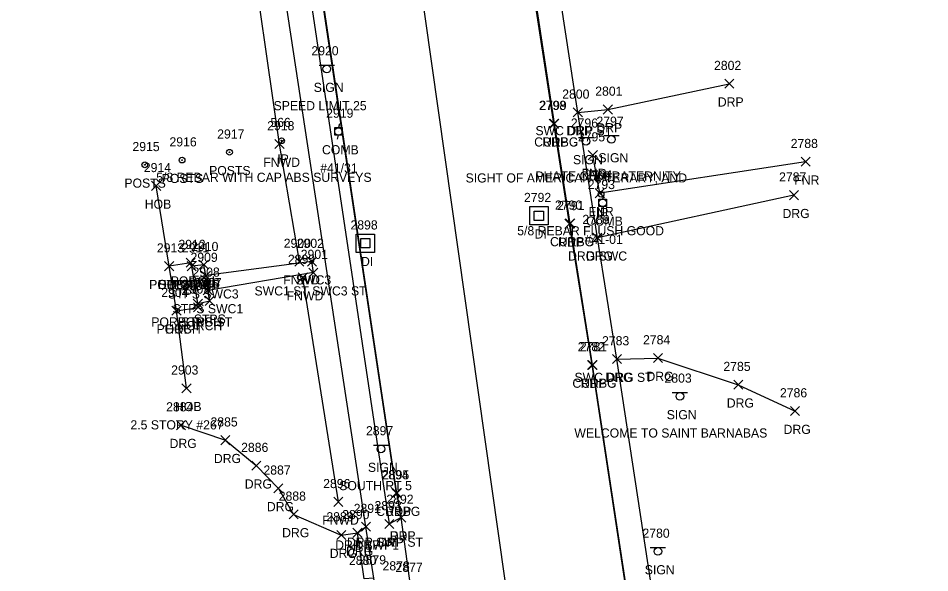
# Model space of a CAD drawing. Extents: x 1690689 to 1696275, y 438760 to 444007.
# Drawn here: x 1691078.4 to 1691277.8, y 441895.7 to 442017 of the extents above; entities that cross this region are included whole.
import ezdxf

# ---------------------------------------------------------------- set-up
doc = ezdxf.new("R2010")
doc.units = 0
for name, color, linetype in [('D_A', 7, 'Continuous'), ('D_I', 7, 'Continuous'), ('DS', 7, 'Continuous'), ('L_A', 7, 'Continuous'), ('L_C', 7, 'Continuous'), ('L_I', 7, 'Continuous'), ('L_TIC', 7, 'Continuous'), ('LBC', 7, 'Continuous'), ('LBF', 7, 'Continuous'), ('LFNC', 7, 'Continuous'), ('LPST', 7, 'Continuous'), ('M_A', 7, 'Continuous'), ('M_C', 7, 'Continuous'), ('M_I', 7, 'Continuous'), ('MPIR', 7, 'Continuous'), ('P_A', 7, 'Continuous'), ('P_I', 7, 'Continuous'), ('P_TIC', 7, 'Continuous'), ('PET', 7, 'Continuous'), ('PRC', 7, 'Continuous'), ('R_A', 7, 'Continuous'), ('R_I', 7, 'Continuous'), ('R_TIC', 7, 'Continuous'), ('RC', 7, 'Continuous'), ('RDG', 7, 'Continuous'), ('RDP', 7, 'Continuous'), ('RSW', 7, 'Continuous'), ('S_A', 7, 'Continuous'), ('S_C', 7, 'Continuous'), ('S_I', 7, 'Continuous'), ('SSGN', 7, 'Continuous'), ('U_A', 7, 'Continuous'), ('U_C', 7, 'Continuous'), ('U_I', 7, 'Continuous'), ('UP', 7, 'Continuous')]:
    doc.layers.add(name, color=color, linetype=linetype)

msp = doc.modelspace()

# ---------------------------------------------------------------- linework, layer by layer
at = {"layer": 'DS'}
for p, q in [((1691190.31, 441975.75), (1691194.31, 441975.75)), ((1691190.31, 441971.75), (1691190.31, 441975.75)), ((1691191.31, 441972.75), (1691191.31, 441974.75)), ((1691191.31, 441974.75), (1691193.31, 441974.75)), ((1691193.31, 441974.75), (1691193.31, 441972.75)), ((1691194.31, 441975.75), (1691194.31, 441971.75)), ((1691193.31, 441972.75), (1691191.31, 441972.75)), ((1691192.31, 441973.76), (1691192.31, 441973.76)), ((1691192.31, 441973.76), (1691192.31, 441973.76)), ((1691194.31, 441971.75), (1691190.31, 441971.75)), ((1691152.36, 441969.75), (1691156.36, 441969.75)), ((1691152.36, 441965.75), (1691152.36, 441969.75)), ((1691153.36, 441966.75), (1691153.36, 441968.75)), ((1691153.36, 441968.75), (1691155.36, 441968.75)), ((1691155.36, 441968.75), (1691155.36, 441966.75)), ((1691156.36, 441969.75), (1691156.36, 441965.75)), ((1691155.36, 441966.75), (1691153.36, 441966.75)), ((1691154.37, 441967.75), (1691154.37, 441967.75)), ((1691154.37, 441967.75), (1691154.37, 441967.75)), ((1691156.36, 441965.75), (1691152.36, 441965.75))]:
    msp.add_line(p, q, dxfattribs=at)
at = {"layer": 'L_TIC'}
for points in [[(1691134.58, 441988.45), (1691136.58, 441990.45)], [(1691136.58, 441988.45), (1691134.58, 441990.45)], [(1691203.11, 441986.02), (1691205.11, 441988.02)], [(1691205.11, 441986.02), (1691203.11, 441988.02)], [(1691249.65, 441984.57), (1691251.65, 441986.57)], [(1691251.65, 441984.57), (1691249.65, 441986.57)], [(1691107.6, 441979.3), (1691109.6, 441981.3)], [(1691109.6, 441979.3), (1691107.6, 441981.3)], [(1691204.66, 441977.7), (1691206.66, 441979.7)], [(1691206.66, 441977.7), (1691204.66, 441979.7)], [(1691115.17, 441962.49), (1691117.17, 441964.49)], [(1691117.17, 441962.49), (1691115.17, 441964.49)], [(1691118.05, 441962.04), (1691120.05, 441964.04)], [(1691120.05, 441962.04), (1691118.05, 441964.04)], [(1691138.93, 441962.74), (1691140.93, 441964.74)], [(1691140.93, 441962.74), (1691138.93, 441964.74)], [(1691110.45, 441961.72), (1691112.45, 441963.72)], [(1691112.45, 441961.72), (1691110.45, 441963.72)], [(1691110.45, 441961.72), (1691112.45, 441963.72)], [(1691112.45, 441961.72), (1691110.45, 441963.72)], [(1691115.38, 441961.72), (1691117.38, 441963.72)], [(1691117.38, 441961.72), (1691115.38, 441963.72)], [(1691115.38, 441961.72), (1691117.38, 441963.72)], [(1691117.38, 441961.72), (1691115.38, 441963.72)], [(1691118.47, 441959.66), (1691120.47, 441961.66)], [(1691120.47, 441959.66), (1691118.47, 441961.66)], [(1691139.69, 441959.24), (1691141.69, 441961.24)], [(1691141.69, 441959.24), (1691139.69, 441961.24)], [(1691118.91, 441956.43), (1691120.91, 441958.43)], [(1691120.91, 441956.43), (1691118.91, 441958.43)], [(1691119.33, 441954.15), (1691121.33, 441956.15)], [(1691121.33, 441954.15), (1691119.33, 441956.15)], [(1691116.71, 441953.53), (1691118.71, 441955.53)], [(1691118.71, 441953.53), (1691116.71, 441955.53)], [(1691116.71, 441953.53), (1691118.71, 441955.53)], [(1691118.71, 441953.53), (1691116.71, 441955.53)], [(1691116.79, 441952.71), (1691118.79, 441954.71)], [(1691118.79, 441952.71), (1691116.79, 441954.71)], [(1691112.07, 441951.99), (1691114.07, 441953.99)], [(1691114.07, 441951.99), (1691112.07, 441953.99)], [(1691112.07, 441951.99), (1691114.07, 441953.99)], [(1691114.07, 441951.99), (1691112.07, 441953.99)], [(1691114.23, 441935.02), (1691116.23, 441937.02)], [(1691116.23, 441935.02), (1691114.23, 441937.02)], [(1691147.46, 441910.18), (1691149.46, 441912.18)], [(1691149.46, 441910.18), (1691147.46, 441912.18)]]:
    msp.add_lwpolyline(points, dxfattribs=at)
at = {"layer": 'LBC'}
msp.add_lwpolyline([(1691115.23, 441936.02), (1691113.07, 441952.99), (1691111.45, 441962.72), (1691108.6, 441980.3)], dxfattribs=at)
at = {"layer": 'LBF'}
for points in [[(1691113.07, 441952.99), (1691117.79, 441953.71), (1691117.71, 441954.53), (1691116.38, 441962.72), (1691116.17, 441963.49), (1691111.45, 441962.72)], [(1691117.71, 441954.53), (1691120.33, 441955.15), (1691119.91, 441957.43), (1691119.47, 441960.66), (1691119.05, 441963.04), (1691116.38, 441962.72)]]:
    msp.add_lwpolyline(points, dxfattribs=at)
at = {"layer": 'LFNC'}
for points in [[(1691139.93, 441963.74), (1691135.58, 441989.45), (1691128.48, 442038.64)], [(1691250.65, 441985.57), (1691205.66, 441978.7), (1691204.11, 441987.02)], [(1691148.46, 441911.18), (1691140.69, 441960.24)]]:
    msp.add_lwpolyline(points, dxfattribs=at)
at = {"layer": 'LPST'}
for centre, radius in [((1691124.65, 441987.64), 0.625), ((1691114.27, 441985.92), 0.625), ((1691114.27, 441985.92), 0.0833), ((1691124.65, 441987.64), 0.0833), ((1691106.12, 441984.89), 0.625), ((1691106.12, 441984.89), 0.0833)]:
    msp.add_circle(centre, radius, dxfattribs=at)
at = {"layer": 'MPIR'}
for centre, radius in [((1691136.04, 441990.17), 0.625), ((1691136.04, 441990.17), 0.0833), ((1691205.92, 441978.48), 0.625), ((1691205.92, 441978.48), 0.0833)]:
    msp.add_circle(centre, radius, dxfattribs=at)
at = {"layer": 'P_TIC'}
for points in [[(1691194.58, 441992.9), (1691196.58, 441994.9)], [(1691196.58, 441992.9), (1691194.58, 441994.9)], [(1691198.02, 441970.98), (1691200.02, 441972.98)], [(1691200.02, 441970.98), (1691198.02, 441972.98)], [(1691202.96, 441940.11), (1691204.96, 441942.11)], [(1691204.96, 441940.11), (1691202.96, 441942.11)], [(1691160.27, 441912.09), (1691162.27, 441914.09)], [(1691162.27, 441912.09), (1691160.27, 441914.09)], [(1691161.22, 441906.75), (1691163.22, 441908.75)], [(1691163.22, 441906.75), (1691161.22, 441908.75)]]:
    msp.add_lwpolyline(points, dxfattribs=at)
at = {"layer": 'PET'}
for points in [[(1691198.82, 441652.13), (1691193.05, 441693.14), (1691192.27, 441697.79), (1691180.43, 441782.55), (1691179.29, 441788.61), (1691177.08, 441805.24), (1691176.38, 441809.81), (1691165.21, 441886.02), (1691164.21, 441892.86), (1691162.22, 441907.75), (1691161.27, 441913.09), (1691143.08, 442034.41), (1691142.3, 442039.49), (1691139.9, 442054.44), (1691139.08, 442060.8), (1691125.85, 442150.15)], [(1691238.35, 441622.76), (1691233.07, 441677.78), (1691233.21, 441686.68), (1691232.89, 441704.26), (1691235.54, 441724.07), (1691224.38, 441802.5), (1691215.77, 441863.02), (1691203.96, 441941.11), (1691199.02, 441971.98), (1691195.58, 441993.9), (1691190.73, 442025.64), (1691172.95, 442147.3)]]:
    msp.add_lwpolyline(points, dxfattribs=at)
at = {"layer": 'PRC'}
msp.add_lwpolyline([(1691277.81, 441080.96), (1691253.5, 441214.94), (1691246.19, 441267.52), (1691239.79, 441327.83), (1691235.79, 441375.29), (1691233.27, 441422.2), (1691229.73, 441505.18), (1691226.6, 441557.92), (1691222.02, 441618.83), (1691218.57, 441657.04), (1691144.02, 442182.42), (1691112.43, 442376.83), (1691097.75, 442454.48), (1691089.73, 442499.13), (1691078.44, 442565.84)], dxfattribs=at)
at = {"layer": 'R_TIC'}
for points in [[(1691232.96, 442001.64), (1691234.96, 442003.64)], [(1691234.96, 442001.64), (1691232.96, 442003.64)], [(1691206.41, 441996.01), (1691208.41, 441998.01)], [(1691208.41, 441996.01), (1691206.41, 441998.01)], [(1691199.85, 441995.37), (1691201.85, 441997.37)], [(1691201.85, 441995.37), (1691199.85, 441997.37)], [(1691199.85, 441995.37), (1691201.85, 441997.37)], [(1691201.85, 441995.37), (1691199.85, 441997.37)], [(1691194.71, 441992.9), (1691196.71, 441994.9)], [(1691196.71, 441992.9), (1691194.71, 441994.9)], [(1691194.71, 441992.9), (1691196.71, 441994.9)], [(1691196.71, 441992.9), (1691194.71, 441994.9)], [(1691247.11, 441977.25), (1691249.11, 441979.25)], [(1691249.11, 441977.25), (1691247.11, 441979.25)], [(1691198.16, 441971.09), (1691200.16, 441973.09)], [(1691200.16, 441971.09), (1691198.16, 441973.09)], [(1691198.16, 441971.09), (1691200.16, 441973.09)], [(1691200.16, 441971.09), (1691198.16, 441973.09)], [(1691204.1, 441967.95), (1691206.1, 441969.95)], [(1691206.1, 441967.95), (1691204.1, 441969.95)], [(1691204.1, 441967.95), (1691206.1, 441969.95)], [(1691206.1, 441967.95), (1691204.1, 441969.95)], [(1691141.69, 441962.73), (1691143.69, 441964.73)], [(1691143.69, 441962.73), (1691141.69, 441964.73)], [(1691142, 441960.32), (1691144, 441962.32)], [(1691144, 441960.32), (1691142, 441962.32)], [(1691142, 441960.32), (1691144, 441962.32)], [(1691144, 441960.32), (1691142, 441962.32)], [(1691118.47, 441959.66), (1691120.47, 441961.66)], [(1691120.47, 441959.66), (1691118.47, 441961.66)], [(1691118.91, 441956.43), (1691120.91, 441958.43)], [(1691120.91, 441956.43), (1691118.91, 441958.43)], [(1691203.07, 441940.13), (1691205.07, 441942.13)], [(1691205.07, 441940.13), (1691203.07, 441942.13)], [(1691203.07, 441940.13), (1691205.07, 441942.13)], [(1691205.07, 441940.13), (1691203.07, 441942.13)], [(1691208.39, 441941.41), (1691210.39, 441943.41)], [(1691210.39, 441941.41), (1691208.39, 441943.41)], [(1691208.39, 441941.41), (1691210.39, 441943.41)], [(1691210.39, 441941.41), (1691208.39, 441943.41)], [(1691217.35, 441941.63), (1691219.35, 441943.63)], [(1691219.35, 441941.63), (1691217.35, 441943.63)], [(1691234.93, 441935.8), (1691236.93, 441937.8)], [(1691236.93, 441935.8), (1691234.93, 441937.8)], [(1691247.35, 441930.03), (1691249.35, 441932.03)], [(1691249.35, 441930.03), (1691247.35, 441932.03)], [(1691113.05, 441926.96), (1691115.05, 441928.96)], [(1691115.05, 441926.96), (1691113.05, 441928.96)], [(1691122.75, 441923.66), (1691124.75, 441925.66)], [(1691124.75, 441923.66), (1691122.75, 441925.66)], [(1691129.51, 441918.09), (1691131.51, 441920.09)], [(1691131.51, 441918.09), (1691129.51, 441920.09)], [(1691134.33, 441913.13), (1691136.33, 441915.13)], [(1691136.33, 441913.13), (1691134.33, 441915.13)], [(1691160.14, 441912.1), (1691162.14, 441914.1)], [(1691162.14, 441912.1), (1691160.14, 441914.1)], [(1691137.67, 441907.43), (1691139.67, 441909.43)], [(1691139.67, 441907.43), (1691137.67, 441909.43)], [(1691161.22, 441906.75), (1691163.22, 441908.75)], [(1691163.22, 441906.75), (1691161.22, 441908.75)], [(1691153.5, 441904.74), (1691155.5, 441906.74)], [(1691155.5, 441904.74), (1691153.5, 441906.74)], [(1691153.5, 441904.74), (1691155.5, 441906.74)], [(1691155.5, 441904.74), (1691153.5, 441906.74)], [(1691158.62, 441905.35), (1691160.62, 441907.35)], [(1691160.62, 441905.35), (1691158.62, 441907.35)], [(1691158.62, 441905.35), (1691160.62, 441907.35)], [(1691160.62, 441905.35), (1691158.62, 441907.35)], [(1691148.09, 441902.91), (1691150.09, 441904.91)], [(1691150.09, 441902.91), (1691148.09, 441904.91)], [(1691151.65, 441903.39), (1691153.65, 441905.39)], [(1691153.65, 441903.39), (1691151.65, 441905.39)], [(1691151.65, 441903.39), (1691153.65, 441905.39)], [(1691153.65, 441903.39), (1691151.65, 441905.39)]]:
    msp.add_lwpolyline(points, dxfattribs=at)
at = {"layer": 'RC'}
for points in [[(1691161.14, 441913.1), (1691142.92, 442034.4)], [(1691195.71, 441993.9), (1691190.89, 442025.7)], [(1691199.16, 441972.09), (1691195.71, 441993.9)], [(1691204.07, 441941.13), (1691199.16, 441972.09)], [(1691233.05, 441704.12), (1691235.66, 441723.91), (1691224.62, 441802.48), (1691215.9, 441863.01), (1691204.07, 441941.13)]]:
    msp.add_lwpolyline(points, dxfattribs=at)
at = {"layer": 'RDG'}
for points in [[(1691248.11, 441978.25), (1691205.1, 441968.95)], [(1691209.39, 441942.41), (1691218.35, 441942.63), (1691235.93, 441936.8), (1691248.35, 441931.03)], [(1691114.05, 441927.96), (1691123.75, 441924.66), (1691130.51, 441919.09), (1691135.33, 441914.13), (1691138.67, 441908.43), (1691149.09, 441903.91), (1691152.65, 441904.39)]]:
    msp.add_lwpolyline(points, dxfattribs=at)
at = {"layer": 'RDP'}
for points in [[(1691200.85, 441996.37), (1691207.41, 441997.01), (1691233.96, 442002.64)], [(1691162.22, 441907.75), (1691159.62, 441906.35)], [(1691156.2, 441894.49), (1691154.13, 441894.37), (1691152.65, 441904.39), (1691154.5, 441905.74)]]:
    msp.add_lwpolyline(points, dxfattribs=at)
at = {"layer": 'RSW'}
for points in [[(1691186.99, 441688.48), (1691175.94, 441757.23), (1691175.52, 441761.59), (1691171.12, 441789.95), (1691169.26, 441802.21), (1691162.18, 441853.19), (1691161.47, 441857.81), (1691156.2, 441894.49), (1691154.5, 441905.74), (1691133.83, 442041.33), (1691132.58, 442050.8), (1691127.44, 442084.38), (1691126.8, 442088.1), (1691113.62, 442174.46)], [(1691235.73, 441762.38), (1691230.02, 441803.11), (1691221.37, 441863.4), (1691209.39, 441942.41), (1691205.1, 441968.95), (1691200.85, 441996.37), (1691196.4, 442025.52), (1691180.16, 442136.25)], [(1691159.62, 441906.35), (1691139.69, 442039.88)], [(1691143, 441961.32), (1691142.69, 441963.73), (1691119.47, 441960.66)], [(1691143, 441961.32), (1691119.91, 441957.43)]]:
    msp.add_lwpolyline(points, dxfattribs=at)
at = {"layer": 'SSGN'}
for p, q in [((1691144.28, 442006.69), (1691147.61, 442006.69)), ((1691145.93, 442005.86), (1691145.93, 442005.86)), ((1691200.99, 441990.88), (1691204.32, 441990.88)), ((1691202.64, 441990.05), (1691202.64, 441990.05)), ((1691206.55, 441991.3), (1691209.88, 441991.3)), ((1691208.19, 441990.46), (1691208.19, 441990.46)), ((1691221.5, 441935.1), (1691224.83, 441935.1)), ((1691223.15, 441934.26), (1691223.15, 441934.26)), ((1691156.13, 441923.59), (1691159.46, 441923.59)), ((1691157.78, 441922.75), (1691157.78, 441922.75)), ((1691216.69, 441901.18), (1691220.02, 441901.18)), ((1691218.34, 441900.34), (1691218.34, 441900.34))]:
    msp.add_line(p, q, dxfattribs=at)
for centre in [(1691145.93, 442005.86), (1691202.64, 441990.05), (1691208.19, 441990.46), (1691223.15, 441934.26), (1691157.78, 441922.75), (1691218.34, 441900.34)]:
    msp.add_circle(centre, 0.833, dxfattribs=at)
at = {"layer": 'UP'}
for p, q in [((1691147.66, 441991.36), (1691147.66, 441993.03)), ((1691147.66, 441993.03), (1691149.32, 441993.03)), ((1691148.74, 441993.86), (1691148.49, 441993.03)), ((1691148.49, 441992.19), (1691148.49, 441992.19)), ((1691149.32, 441993.03), (1691149.32, 441991.36)), ((1691149.32, 441991.36), (1691147.66, 441991.36)), ((1691148.24, 441990.53), (1691148.49, 441991.36)), ((1691206.51, 441978.25), (1691206.26, 441977.42)), ((1691205.43, 441975.75), (1691205.43, 441977.42)), ((1691205.43, 441977.42), (1691207.09, 441977.42)), ((1691206.26, 441976.59), (1691206.26, 441976.59)), ((1691207.09, 441977.42), (1691207.09, 441975.75)), ((1691207.09, 441975.75), (1691205.43, 441975.75)), ((1691206.01, 441974.92), (1691206.26, 441975.75))]:
    msp.add_line(p, q, dxfattribs=at)
for centre in [(1691148.49, 441992.19), (1691206.26, 441976.59)]:
    msp.add_circle(centre, 0.833, dxfattribs=at)

# ---------------------------------------------------------------- texts
at = {"layer": 'D_A'}
for p in [(1691191.37, 441968.76), (1691153.42, 441962.75)]:
    msp.add_text('DI', height=2, dxfattribs=at).set_placement(p)
at = {"layer": 'D_I'}
for s, p in [('2792', (1691189.05, 441976.76)), ('2898', (1691151.11, 441970.75))]:
    msp.add_text(s, height=2, dxfattribs=at).set_placement(p)
at = {"layer": 'L_A'}
for s, p in [('FNWD', (1691132.05, 441984.45)), ('POSTS', (1691120.19, 441982.64)), ('FNR', (1691201.64, 441982.02)), ('POSTS', (1691101.66, 441979.89)), ('POSTS', (1691109.81, 441980.92)), ('FNR', (1691248.18, 441980.57)), ('HOB', (1691106.11, 441975.3)), ('FNR', (1691203.19, 441973.7)), ('PORCH', (1691111.79, 441958.49)), ('STPS', (1691115.57, 441958.04)), ('FNWD', (1691136.4, 441958.74)), ('PORCH', (1691107.07, 441957.72)), ('HOB', (1691108.95, 441957.72)), ('STPS POR', (1691109.08, 441957.72)), ('PORCH', (1691112, 441957.72)), ('STPS SWC3', (1691111.19, 441955.66)), ('FNWD', (1691137.15, 441955.24)), ('STPS SWC1', (1691112.19, 441952.43)), ('STPS', (1691116.85, 441950.15)), ('POR STPS ST', (1691107.54, 441949.53)), ('PORCH', (1691108.69, 441947.99)), ('HOB', (1691110.58, 441947.99)), ('PORCH', (1691113.33, 441949.53)), ('PORCH', (1691113.41, 441948.71)), ('HOB', (1691112.74, 441931.02)), ('FNWD', (1691144.92, 441906.18))]:
    msp.add_text(s, height=2, dxfattribs=at).set_placement(p)
at = {"layer": 'L_C'}
msp.add_text('2.5 STORY #267', height=2, dxfattribs=at).set_placement((1691102.98, 441927.02))
at = {"layer": 'L_I'}
for s, p in [('2918', (1691132.89, 441992.45)), ('2917', (1691121.96, 441990.64)), ('2795', (1691200.85, 441990.02)), ('2915', (1691103.42, 441987.89)), ('2916', (1691111.52, 441988.92)), ('2788', (1691247.39, 441988.57)), ('2914', (1691105.91, 441983.3)), ('2794', (1691202.4, 441981.7)), ('2912', (1691113.47, 441966.49)), ('2910', (1691116.27, 441966.04)), ('2900', (1691136.51, 441966.74)), ('2913', (1691108.76, 441965.72)), ('2913', (1691108.76, 441965.72)), ('2911', (1691114.25, 441965.72)), ('2911', (1691114.25, 441965.72)), ('2909', (1691116.12, 441963.66)), ('2899', (1691137.42, 441963.24)), ('2908', (1691116.57, 441960.43)), ('2907', (1691116.99, 441958.15)), ('2904', (1691109.73, 441955.99)), ('2904', (1691109.73, 441955.99)), ('2906', (1691114.31, 441957.53)), ('2906', (1691114.31, 441957.53)), ('2905', (1691114.45, 441956.71)), ('2903', (1691111.89, 441939.02)), ('2896', (1691145.14, 441914.18))]:
    msp.add_text(s, height=2, dxfattribs=at).set_placement(p)
at = {"layer": 'M_A'}
for p in [(1691135.09, 441985.17), (1691204.97, 441973.48)]:
    msp.add_text('IP', height=2, dxfattribs=at).set_placement(p)
at = {"layer": 'M_C'}
for s, p in [('5/8 REBAR WITH CAP ABS SURVEYS', (1691108.62, 441981.17)), ('5/8 REBAR FLUSH GOOD', (1691187.58, 441969.48))]:
    msp.add_text(s, height=2, dxfattribs=at).set_placement(p)
at = {"layer": 'M_I'}
for s, p in [('566', (1691133.58, 441993.17)), ('560', (1691203.43, 441981.48))]:
    msp.add_text(s, height=2, dxfattribs=at).set_placement(p)
at = {"layer": 'P_A'}
for p in [(1691193.06, 441988.9), (1691196.51, 441966.98), (1691201.45, 441936.11), (1691158.76, 441908.09), (1691159.7, 441902.75)]:
    msp.add_text('RDP', height=2, dxfattribs=at).set_placement(p)
at = {"layer": 'P_I'}
for s, p in [('2798', (1691192.32, 441996.9)), ('2791', (1691196.33, 441974.98)), ('2781', (1691201.27, 441944.11)), ('2895', (1691158.01, 441916.09)), ('2892', (1691158.96, 441910.75)), ('2877', (1691160.95, 441895.86))]:
    msp.add_text(s, height=2, dxfattribs=at).set_placement(p)
at = {"layer": 'R_A'}
for s, p in [('DRP', (1691231.45, 441997.64)), ('DRP', (1691204.9, 441992.01)), ('SWC DRP ST', (1691191.56, 441991.37)), ('DRP', (1691198.33, 441991.37)), ('CURBG', (1691191.29, 441988.9)), ('CURBC', (1691191.29, 441988.9)), ('DRG', (1691245.6, 441973.25)), ('CURBC', (1691194.75, 441967.09)), ('CURBG', (1691194.75, 441967.09)), ('DRG SWC', (1691198.69, 441963.95)), ('DRG', (1691202.59, 441963.95)), ('SWC3', (1691139.16, 441958.73)), ('SWC1 ST SWC3 ST', (1691130.12, 441956.32)), ('SWC1 ST SWC3 ST', (1691130.12, 441956.32)), ('STPS SWC3', (1691111.19, 441955.66)), ('STPS SWC1', (1691112.19, 441952.43)), ('CURBG', (1691199.65, 441936.13)), ('CURBC', (1691199.65, 441936.13)), ('SWC DRG ST', (1691200.1, 441937.41)), ('DRG', (1691206.87, 441937.41)), ('DRG', (1691215.84, 441937.63)), ('DRG', (1691233.41, 441931.8)), ('DRG', (1691245.84, 441926.03)), ('DRG', (1691111.54, 441922.96)), ('DRG', (1691121.23, 441919.66)), ('DRG', (1691127.99, 441914.09)), ('DRG', (1691132.82, 441909.13)), ('CURBG', (1691156.73, 441908.1)), ('DRG', (1691136.16, 441903.43)), ('DRP', (1691159.7, 441902.75)), ('DRP SWP1', (1691147.76, 441900.74)), ('DRP SWP ST', (1691150.33, 441901.35)), ('DRP', (1691151.99, 441900.74)), ('DRP', (1691157.1, 441901.35)), ('DRG', (1691146.58, 441898.91)), ('DRG', (1691150.14, 441899.39)), ('DRP', (1691150.14, 441899.39))]:
    msp.add_text(s, height=2, dxfattribs=at).set_placement(p)
at = {"layer": 'R_I'}
for s, p in [('2802', (1691230.62, 442005.64)), ('2801', (1691204.64, 442000.01)), ('2800', (1691197.42, 441999.37)), ('2800', (1691197.42, 441999.37)), ('2799', (1691192.44, 441996.9)), ('2799', (1691192.44, 441996.9)), ('2787', (1691244.85, 441981.25)), ('2790', (1691195.82, 441975.09)), ('2790', (1691195.82, 441975.09)), ('2789', (1691201.83, 441971.95)), ('2789', (1691201.83, 441971.95)), ('2902', (1691139.35, 441966.73)), ('2901', (1691140.23, 441964.32)), ('2901', (1691140.23, 441964.32)), ('2909', (1691116.12, 441963.66)), ('2908', (1691116.57, 441960.43)), ('2782', (1691200.81, 441944.13)), ('2782', (1691200.81, 441944.13)), ('2783', (1691206.13, 441945.41)), ('2783', (1691206.13, 441945.41)), ('2784', (1691215.09, 441945.63)), ('2785', (1691232.67, 441939.8)), ('2786', (1691245.04, 441934.03)), ('2884', (1691110.79, 441930.96)), ('2885', (1691120.49, 441927.66)), ('2886', (1691127.19, 441922.09)), ('2887', (1691132.07, 441917.13)), ('2894', (1691157.88, 441916.1)), ('2888', (1691135.41, 441911.43)), ('2892', (1691158.96, 441910.75)), ('2891', (1691151.81, 441908.74)), ('2891', (1691151.81, 441908.74)), ('2893', (1691156.36, 441909.35)), ('2893', (1691156.36, 441909.35)), ('2889', (1691145.83, 441906.91)), ('2890', (1691149.3, 441907.39)), ('2890', (1691149.3, 441907.39)), ('2880', (1691150.78, 441897.37)), ('2880', (1691150.78, 441897.37)), ('2879', (1691152.93, 441897.49)), ('2879', (1691152.93, 441897.49)), ('2878', (1691158.12, 441896.18)), ('2878', (1691158.12, 441896.18)), ('2877', (1691160.95, 441895.86))]:
    msp.add_text(s, height=2, dxfattribs=at).set_placement(p)
at = {"layer": 'S_A'}
for p in [(1691143.07, 442000.84), (1691199.77, 441985.03), (1691205.33, 441985.44), (1691220.28, 441929.24), (1691154.92, 441917.73), (1691215.47, 441895.32)]:
    msp.add_text('SIGN', height=2, dxfattribs=at).set_placement(p)
at = {"layer": 'S_C'}
for s, p in [('SPEED LIMIT 25', (1691134.29, 441996.84)), ('SIGHT OF AMERICAN LITERARY, AND', (1691176.29, 441981.03)), ('PHATE CHI FRATERNITY', (1691191.56, 441981.44)), ('WELCOME TO SAINT BARNABAS', (1691200.07, 441925.24)), ('SOUTH RT 5', (1691148.64, 441913.73))]:
    msp.add_text(s, height=2, dxfattribs=at).set_placement(p)
at = {"layer": 'S_I'}
for s, p in [('2920', (1691142.56, 442008.84)), ('2796', (1691199.3, 441993.03)), ('2797', (1691204.91, 441993.44)), ('2803', (1691219.79, 441937.24)), ('2897', (1691154.5, 441925.73)), ('2780', (1691214.97, 441903.32))]:
    msp.add_text(s, height=2, dxfattribs=at).set_placement(p)
at = {"layer": 'U_A'}
for p in [(1691144.88, 441987.19), (1691202.65, 441971.59)]:
    msp.add_text('COMB', height=2, dxfattribs=at).set_placement(p)
at = {"layer": 'U_C'}
for s, p in [('#41/31', (1691144.49, 441983.19)), ('#41-01', (1691202.34, 441967.59))]:
    msp.add_text(s, height=2, dxfattribs=at).set_placement(p)
at = {"layer": 'U_I'}
for s, p in [('2919', (1691145.79, 441995.19)), ('2793', (1691203, 441979.59))]:
    msp.add_text(s, height=2, dxfattribs=at).set_placement(p)

doc.saveas('drawing.dxf')
